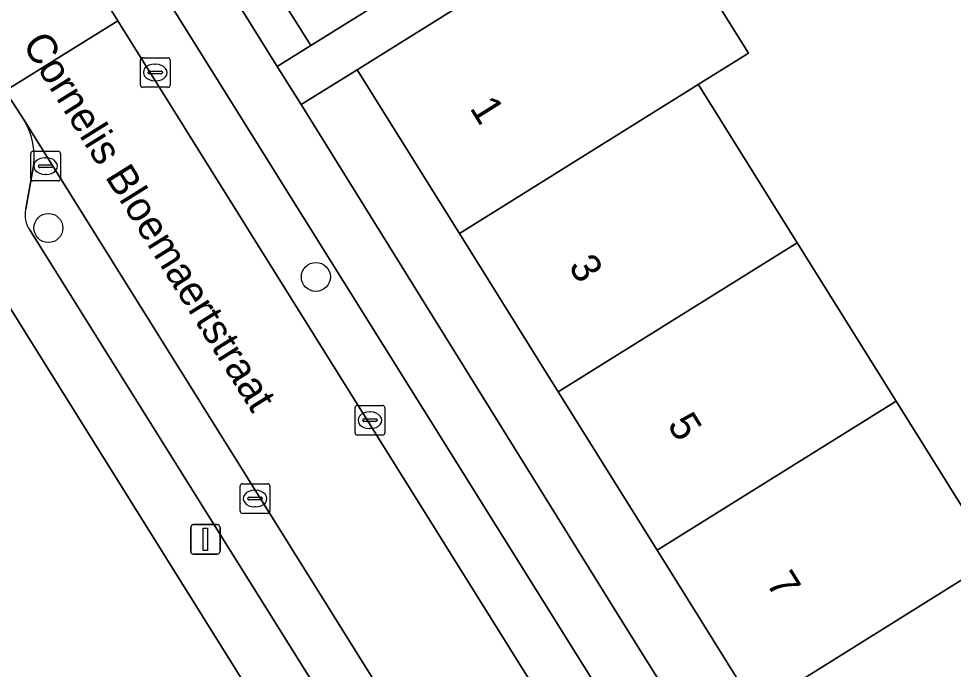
# Model space of a CAD drawing. Extents: x 159664 to 160323, y 385312 to 386115.
# Drawn here: x 159966.33 to 159997.86, y 385941.4 to 385963.35 of the extents above; entities that cross this region are included whole.
import ezdxf

# ---------------------------------------------------------------- set-up
doc = ezdxf.new("R2010")
doc.units = 0
for name, color, linetype in [('IMGEO_Boom', 7, 'Continuous'), ('IMGEO_Erf', 7, 'Continuous'), ('IMGEO_Kolk', 7, 'Continuous'), ('IMGEO_Lichtmast', 7, 'Continuous'), ('IMGEO_Openbare_ruimte_label', 7, 'Continuous'), ('IMGEO_Pand', 7, 'Continuous'), ('IMGEO_Pand_nummerreeks', 7, 'Continuous'), ('IMGEO_Parkeervlak_open', 7, 'Continuous'), ('IMGEO_Rijbaan_lokaal_open', 7, 'Continuous'), ('IMGEO_Voetpad_open', 7, 'Continuous')]:
    doc.layers.add(name, color=color, linetype=linetype)

msp = doc.modelspace()

# ---------------------------------------------------------------- linework, layer by layer
at = {"layer": 'IMGEO_Boom'}
for centre in [(159967.33, 385956.286), (159976.353, 385954.636)]:
    msp.add_circle(centre, 0.489, dxfattribs=at)
at = {"layer": 'IMGEO_Erf'}
for points in [[(159947.685, 386005.559), (159971.661, 385967.195), (159975.052, 385961.74), (159976.18, 385962.441), (159973.428, 385966.833), (159974.165, 385967.295), (159973.172, 385968.889), (159971.714, 385971.226), (159970.719, 385971.449), (159969.785, 385972.954), (159970.015, 385973.953), (159969.85, 385974.216), (159969.709, 385974.434), (159968.72, 385974.665), (159967.795, 385976.161), (159968.015, 385977.165), (159966.505, 385979.583), (159965.549, 385981.11), (159964.803, 385980.644), (159962.29, 385984.673), (159960.483, 385987.566), (159960.763, 385988.77), (159959.575, 385990.666), (159958.126, 385992.973)], [(159998.995, 385974.89), (159987.5, 385967.716), (159990.948, 385962.189), (159989.251, 385961.13), (159989.302, 385961.049), (159992.59, 385955.788), (159995.93, 385950.446), (159999.264, 385945.112)], [(159965.644, 385935.647), (159967.39, 385934.915), (159969.912, 385936.286), (159968.127, 385939.157), (159970.828, 385940.836), (159972.612, 385937.965), (159974.902, 385939.389), (159960.488, 385962.471)]]:
    msp.add_lwpolyline(points, dxfattribs=at)
msp.add_lwpolyline([(159991.196, 385940.076), (159987.865, 385945.413), (159984.529, 385950.757), (159981.194, 385956.102), (159977.747, 385961.624), (159975.855, 385960.448), (159986.636, 385943.101), (160009.458, 385906.629), (160011.351, 385907.814), (160007.893, 385913.355), (160007.779, 385913.539), (160008.364, 385913.904), (160005.142, 385919.064), (160001.8, 385924.418), (159998.592, 385929.556), (159997.409, 385928.817), (159997.28, 385929.023), (159993.946, 385934.366), (159993.835, 385934.544), (159994.42, 385934.909)], close=True, dxfattribs=at)
at = {"layer": 'IMGEO_Kolk'}
for p, q in [((159970.436, 385961.107), (159970.436, 385961.959)), ((159970.511, 385962.033), (159971.363, 385962.033)), ((159971.437, 385961.959), (159971.437, 385961.107)), ((159970.924, 385961.813), (159970.949, 385961.813)), ((159970.695, 385961.527), (159970.695, 385961.539)), ((159971.133, 385961.49), (159970.735, 385961.49)), ((159970.738, 385961.576), (159971.136, 385961.576)), ((159971.179, 385961.539), (159971.179, 385961.527)), ((159971.363, 385961.033), (159970.511, 385961.033)), ((159970.947, 385961.253), (159970.922, 385961.253)), ((159966.735, 385957.948), (159966.735, 385958.8)), ((159966.81, 385958.874), (159967.662, 385958.874)), ((159967.736, 385958.8), (159967.736, 385957.948)), ((159967.223, 385958.654), (159967.248, 385958.654)), ((159966.994, 385958.368), (159966.994, 385958.38)), ((159967.432, 385958.331), (159967.034, 385958.331)), ((159967.037, 385958.417), (159967.435, 385958.417)), ((159967.478, 385958.38), (159967.478, 385958.368)), ((159967.662, 385957.874), (159966.81, 385957.874)), ((159967.246, 385958.094), (159967.221, 385958.094)), ((159977.753, 385950.3), (159978.605, 385950.3)), ((159977.678, 385949.374), (159977.678, 385950.226)), ((159978.166, 385950.08), (159978.191, 385950.08)), ((159978.679, 385950.226), (159978.679, 385949.374)), ((159977.937, 385949.794), (159977.937, 385949.806)), ((159978.375, 385949.757), (159977.977, 385949.757)), ((159977.98, 385949.843), (159978.378, 385949.843)), ((159978.421, 385949.806), (159978.421, 385949.794)), ((159978.189, 385949.52), (159978.164, 385949.52)), ((159978.605, 385949.3), (159977.753, 385949.3)), ((159973.801, 385946.732), (159973.801, 385947.584)), ((159973.876, 385947.658), (159974.728, 385947.658)), ((159974.289, 385947.438), (159974.314, 385947.438)), ((159974.802, 385947.584), (159974.802, 385946.732)), ((159974.06, 385947.152), (159974.06, 385947.164)), ((159974.498, 385947.115), (159974.1, 385947.115)), ((159974.103, 385947.201), (159974.501, 385947.201)), ((159974.544, 385947.164), (159974.544, 385947.152)), ((159974.312, 385946.878), (159974.287, 385946.878)), ((159974.728, 385946.658), (159973.876, 385946.658))]:
    msp.add_line(p, q, dxfattribs=at)
for points in [[(159970.436, 385961.107), (159970.436, 385961.959)], [(159970.511, 385962.033), (159971.363, 385962.033)], [(159971.437, 385961.959), (159971.437, 385961.107)], [(159971.363, 385961.033), (159970.511, 385961.033)], [(159966.735, 385957.948), (159966.735, 385958.8)], [(159966.81, 385958.874), (159967.662, 385958.874)], [(159967.736, 385958.8), (159967.736, 385957.948)], [(159967.662, 385957.874), (159966.81, 385957.874)], [(159977.753, 385950.3), (159978.605, 385950.3)], [(159977.678, 385949.374), (159977.678, 385950.226)], [(159978.679, 385950.226), (159978.679, 385949.374)], [(159978.605, 385949.3), (159977.753, 385949.3)], [(159973.801, 385946.732), (159973.801, 385947.584)], [(159973.876, 385947.658), (159974.728, 385947.658)], [(159974.802, 385947.584), (159974.802, 385946.732)], [(159974.728, 385946.658), (159973.876, 385946.658)]]:
    msp.add_lwpolyline(points, dxfattribs=at)
for centre, radius, start, end in [((159970.513, 385961.957), 0.0765, 91.552, 178.448), ((159970.513, 385961.957), 0.0765, 91.552, 178.448), ((159971.361, 385961.957), 0.0765, 1.552, 88.448), ((159971.361, 385961.957), 0.0765, 1.552, 88.448), ((159970.735, 385961.536), 0.0403, 85.8775, 175.7526), ((159970.732, 385961.526), 0.0366, 178.938, 274.7102), ((159971.136, 385961.533), 0.043, 264.8664, 352.4533), ((159971.14, 385961.538), 0.0386, 1.7309, 96.639), ((159970.513, 385961.109), 0.0765, 181.552, 268.448), ((159970.513, 385961.109), 0.0765, 181.552, 268.448), ((159971.361, 385961.109), 0.0765, 271.552, 358.448), ((159971.361, 385961.109), 0.0765, 271.552, 358.448), ((159966.812, 385958.798), 0.0765, 91.552, 178.448), ((159966.812, 385958.798), 0.0765, 91.552, 178.448), ((159967.66, 385958.798), 0.0765, 1.552, 88.448), ((159967.66, 385958.798), 0.0765, 1.552, 88.448), ((159967.034, 385958.377), 0.0403, 85.8775, 175.7526), ((159967.031, 385958.367), 0.0366, 178.938, 274.7102), ((159967.435, 385958.374), 0.043, 264.8664, 352.4533), ((159967.439, 385958.379), 0.0386, 1.7309, 96.639), ((159966.812, 385957.95), 0.0765, 181.552, 268.448), ((159966.812, 385957.95), 0.0765, 181.552, 268.448), ((159967.66, 385957.95), 0.0765, 271.552, 358.448), ((159967.66, 385957.95), 0.0765, 271.552, 358.448), ((159977.755, 385950.224), 0.0765, 91.552, 178.448), ((159977.755, 385950.224), 0.0765, 91.552, 178.448), ((159978.603, 385950.224), 0.0765, 1.552, 88.448), ((159978.603, 385950.224), 0.0765, 1.552, 88.448), ((159977.977, 385949.803), 0.0403, 85.8775, 175.7526), ((159977.974, 385949.793), 0.0366, 178.938, 274.7102), ((159978.378, 385949.8), 0.043, 264.8664, 352.4533), ((159978.382, 385949.805), 0.0386, 1.7309, 96.639), ((159977.755, 385949.376), 0.0765, 181.552, 268.448), ((159977.755, 385949.376), 0.0765, 181.552, 268.448), ((159978.603, 385949.376), 0.0765, 271.552, 358.448), ((159978.603, 385949.376), 0.0765, 271.552, 358.448), ((159973.878, 385947.582), 0.0765, 91.552, 178.448), ((159973.878, 385947.582), 0.0765, 91.552, 178.448), ((159974.726, 385947.582), 0.0765, 1.552, 88.448), ((159974.726, 385947.582), 0.0765, 1.552, 88.448), ((159974.1, 385947.161), 0.0403, 85.8775, 175.7526), ((159974.097, 385947.151), 0.0366, 178.938, 274.7102), ((159974.501, 385947.158), 0.043, 264.8664, 352.4533), ((159974.505, 385947.163), 0.0386, 1.7309, 96.639), ((159973.878, 385946.734), 0.0765, 181.552, 268.448), ((159973.878, 385946.734), 0.0765, 181.552, 268.448), ((159974.726, 385946.734), 0.0765, 271.552, 358.448), ((159974.726, 385946.734), 0.0765, 271.552, 358.448)]:
    msp.add_arc(centre, radius, start, end, dxfattribs=at)
for centre, major_axis, ratio, start_param, end_param in [((159970.923, 385961.533), (-0.387, 0.002), 0.722429, 4.712389, 7.853982), ((159970.948, 385961.533), (-0.39, 0.002), 0.717154, 1.570796, 4.712389), ((159967.222, 385958.374), (-0.387, 0.002), 0.722429, 4.712389, 7.853982), ((159967.247, 385958.374), (-0.39, 0.002), 0.717154, 1.570796, 4.712389), ((159978.165, 385949.8), (-0.387, 0.002), 0.722429, 4.712389, 7.853982), ((159978.19, 385949.8), (-0.39, 0.002), 0.717154, 1.570796, 4.712389), ((159974.288, 385947.158), (-0.387, 0.002), 0.722429, 4.712389, 7.853982), ((159974.313, 385947.158), (-0.39, 0.002), 0.717154, 1.570796, 4.712389)]:
    msp.add_ellipse(centre, major_axis=major_axis, ratio=ratio, start_param=start_param, end_param=end_param, dxfattribs=at)
at = {"layer": 'IMGEO_Lichtmast'}
for p, q in [((159972.131, 385945.381), (159972.131, 385946.181)), ((159972.131, 385946.181), (159972.131, 385945.381)), ((159972.231, 385946.281), (159973.021, 385946.281)), ((159973.021, 385946.281), (159972.231, 385946.281)), ((159973.121, 385946.181), (159973.121, 385945.381)), ((159973.121, 385945.381), (159973.121, 385946.181)), ((159973.021, 385945.281), (159972.231, 385945.281)), ((159972.231, 385945.281), (159973.021, 385945.281))]:
    msp.add_line(p, q, dxfattribs=at)
msp.add_lwpolyline([(159972.551, 385946.156), (159972.701, 385946.156), (159972.701, 385945.406), (159972.551, 385945.406), (159972.551, 385946.156)], dxfattribs=at)
for centre, start, end in [((159972.231, 385946.181), 90, 180), ((159972.231, 385946.181), 90, 180), ((159973.021, 385946.181), 0, 90), ((159973.021, 385946.181), 360, 90), ((159972.231, 385945.381), 180, 270), ((159972.231, 385945.381), 180, 270), ((159973.021, 385945.381), 270, 0), ((159973.021, 385945.381), 270, 0)]:
    msp.add_arc(centre, 0.1, start, end, dxfattribs=at)
at = {"layer": 'IMGEO_Pand'}
for points in [[(159984.468, 385975.935), (159973.172, 385968.889), (159974.165, 385967.295), (159973.428, 385966.833), (159976.18, 385962.441), (159983.333, 385966.903), (159980.964, 385970.692), (159985.793, 385973.719), (159985.837, 385973.746), (159985.8, 385973.805)], [(159990.948, 385962.189), (159987.5, 385967.716), (159977.747, 385961.624), (159981.194, 385956.102), (159989.251, 385961.13)], [(159989.302, 385961.049), (159989.251, 385961.13), (159981.194, 385956.102), (159984.529, 385950.757), (159992.59, 385955.788)], [(159984.529, 385950.757), (159987.865, 385945.413), (159995.93, 385950.446), (159992.59, 385955.788)], [(159999.264, 385945.112), (159995.93, 385950.446), (159987.865, 385945.413), (159991.196, 385940.076)], [(160002.604, 385939.77), (160002.495, 385939.944), (159999.264, 385945.112), (159991.196, 385940.076), (159994.42, 385934.909), (159994.531, 385934.731)]]:
    msp.add_lwpolyline(points, close=True, dxfattribs=at)
at = {"layer": 'IMGEO_Parkeervlak_open'}
for points in [[(160007.649, 385905.881), (159928.962, 386031.821)], [(159959.016, 385980.344), (159969.672, 385963.279)], [(159969.672, 385963.279), (160009.352, 385899.733)], [(160005.572, 385897.372), (159966.516, 385959.929)], [(159966.835, 385958.438), (159966.569, 385956.931)], [(159966.714, 385956.197), (160000.735, 385901.781)]]:
    msp.add_lwpolyline(points, dxfattribs=at)
for centre, radius, start, end in [((159964.41, 385958.699), 2.439, 353.8649, 30.2879), ((159967.448, 385956.723), 0.903, 166.7128, 215.6368)]:
    msp.add_arc(centre, radius, start, end, dxfattribs=at)
at = {"layer": 'IMGEO_Rijbaan_lokaal_open'}
msp.add_lwpolyline([(159964.885, 385962.489), (159965.877, 385960.911), (159969.672, 385963.279), (159959.016, 385980.344)], dxfattribs=at)
msp.add_lwpolyline([(160009.352, 385899.733), (159969.672, 385963.279), (159965.877, 385960.911), (159966.516, 385959.929), (160005.572, 385897.372)], close=True, dxfattribs=at)
at = {"layer": 'IMGEO_Voetpad_open'}
for points in [[(160035.946, 385864.298), (160011.524, 385903.327), (160009.458, 385906.629), (159986.636, 385943.101), (159975.855, 385960.448), (159975.052, 385961.74), (159971.661, 385967.195), (159947.685, 386005.559), (159946.972, 386006.7), (159927.976, 386037.096), (159924.811, 386035.12), (159925.856, 386033.371)], [(159928.962, 386031.821), (160007.649, 385905.881), (160007.996, 385906.094), (160010.404, 385902.292), (160010.038, 385902.057), (160043.232, 385848.929)], [(159999.836, 385977.277), (159983.333, 385966.903), (159976.18, 385962.441), (159975.052, 385961.74), (159975.855, 385960.448), (159977.747, 385961.624), (159987.5, 385967.716), (159998.995, 385974.89)], [(159958.817, 385965.147), (159960.488, 385962.471), (159974.902, 385939.389), (159974.915, 385939.368), (159975.723, 385938.075), (159999.31, 385900.303), (160001.374, 385896.998), (160024.965, 385859.219), (160022.665, 385857.784), (160023.444, 385856.494), (160025.732, 385857.953), (160038.523, 385837.501), (160040.915, 385833.676)], [(159966.516, 385959.929), (159965.877, 385960.911), (159964.885, 385962.489)], [(159966.569, 385956.931), (159966.835, 385958.438)], [(160036.27, 385844.777), (160003.077, 385897.951), (160002.698, 385897.724), (160000.327, 385901.513), (160000.735, 385901.781), (159966.714, 385956.197)]]:
    msp.add_lwpolyline(points, dxfattribs=at)
for centre, radius, start, end in [((159964.41, 385958.699), 2.439, 353.8649, 30.2879), ((159967.448, 385956.723), 0.903, 166.7128, 215.6368)]:
    msp.add_arc(centre, radius, start, end, dxfattribs=at)

# ---------------------------------------------------------------- texts
at = {"layer": 'IMGEO_Openbare_ruimte_label'}
msp.add_text('Cornelis Bloemaertstraat', height=1, rotation=301.9568, dxfattribs=at).set_placement((159966.431, 385962.496))
at = {"layer": 'IMGEO_Pand_nummerreeks'}
for s, rotation, p in [('1', 301.9708, (159981.523, 385960.334)), ('3', 301.9708, (159984.855, 385954.994)), ('5', 301.9685, (159988.191, 385949.65)), ('7', 301.9685, (159991.524, 385944.309))]:
    msp.add_text(s, height=1, rotation=rotation, dxfattribs=at).set_placement(p)

doc.saveas('drawing.dxf')
